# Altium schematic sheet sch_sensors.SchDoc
size Letter
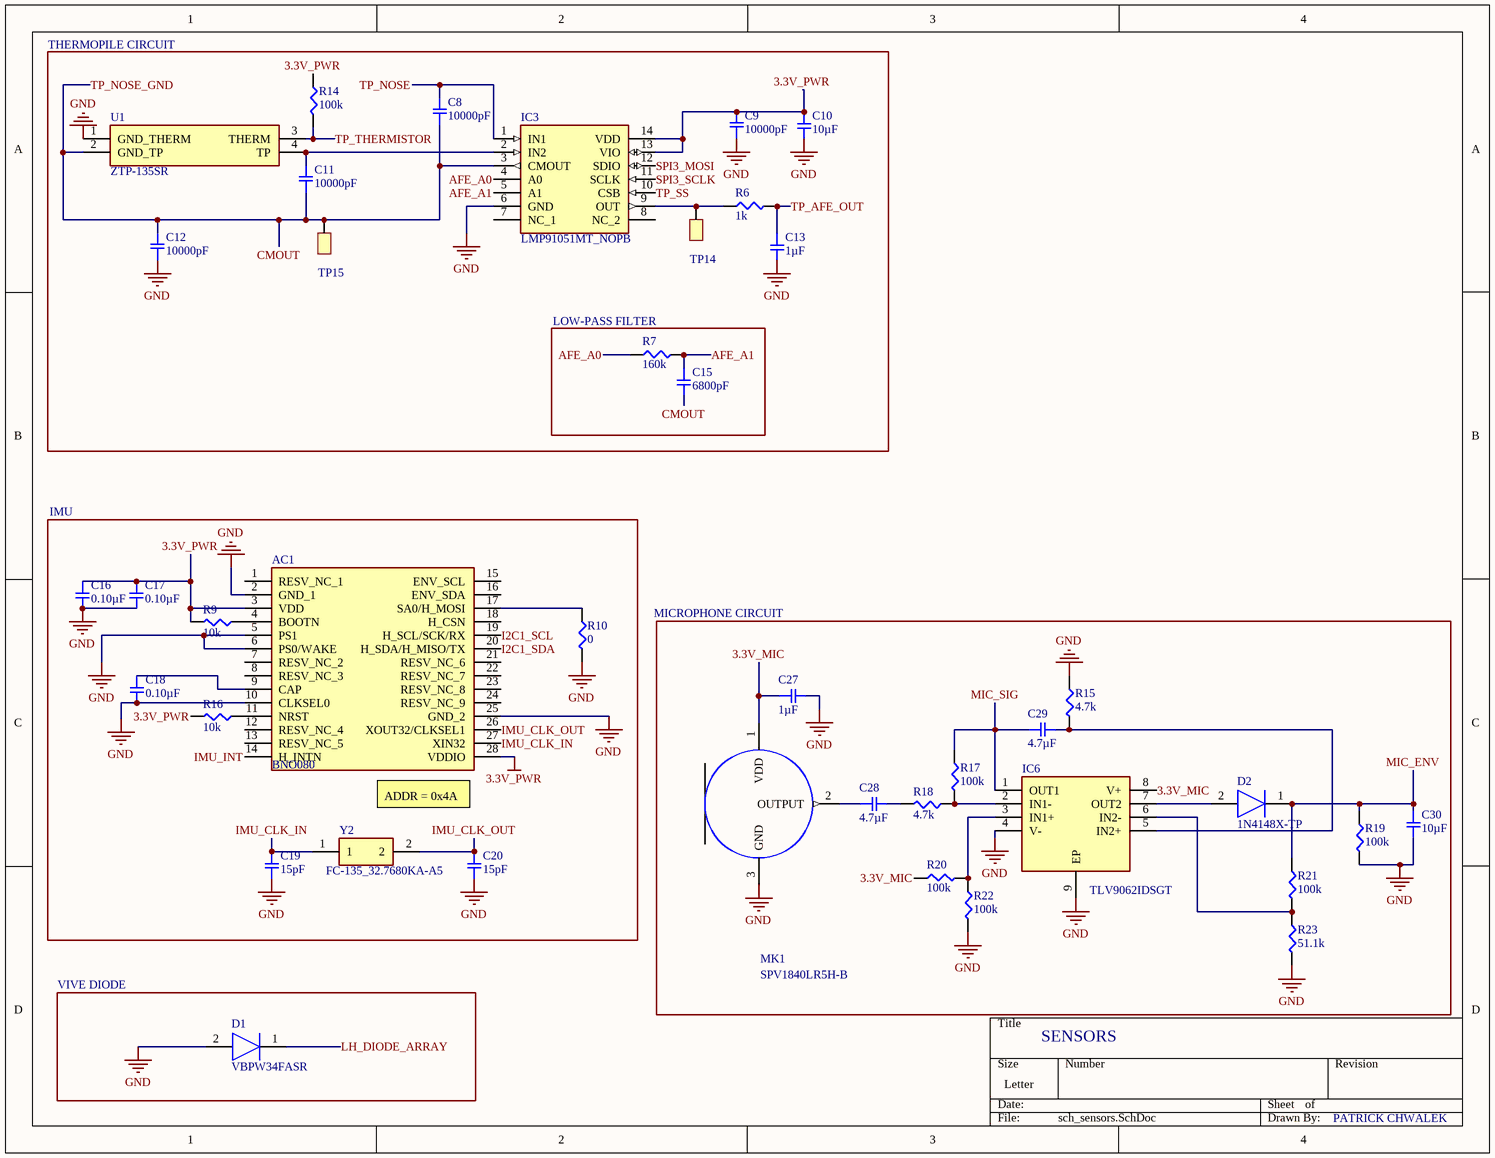
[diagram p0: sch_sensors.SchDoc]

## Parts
AC1  BNO080  [BNO080]
C8  10000pF  [SMD-0402C]
C9  10000pF  [SMD-0402C]
C10  10µF  [SMD-0402C]
C11  10000pF  [SMD-0402C]
C12  10000pF  [SMD-0402C]
C13  1µF  [SMD-0402C]
C15  6800pF  [SMD-0402C]
C16  0.10µF  [CAPC1005X55N]
C17  0.10µF  [CAPC1005X55N]
C18  0.10µF  [CAPC1005X55N]
C19  15pF  [CAPC1005X55N]
C20  15pF  [CAPC1005X55N]
C27  1µF  [SMD-0402-RES]
C28  4.7µF  [SMD-0402C]
C29  4.7µF  [SMD-0402C]
C30  10µF  [SMD-0402C]
D1  VBPW34FASR  [VBPW34FASR]
D2  1N4148X-TP  [SODFL1608X70N]
IC3  LMP91051MT_NOPB  [SOP65P640X120-14N]
IC6  TLV9062IDSGT  [SON50P200X200X80-9N]
MK1  SPV1840LR5H-B  [*MIC_SPV1840LR5H-B]
R6  1k  [SMD-0402-RES]
R7  160k  [SMD-0402-RES]
R9  10k  [SMD-0402-RES]
R10  0  [SMD-0402-RES]
R14  100k  [SMD-0402-RES]
R15  4.7k  [SMD-0402-RES]
R16  10k  [SMD-0402-RES]
R17  100k  [SMD-0402-RES]
R18  4.7k  [SMD-0402-RES]
R19  100k  [SMD-0402-RES]
R20  100k  [SMD-0402-RES]
R21  100k  [SMD-0402-RES]
R22  100k  [SMD-0402-RES]
R23  51.1k  [SMD-0402-RES]
TP14  TestPoint  [TestPoint_0.4mm]  (value not drawn)
TP15  TestPoint  [TestPoint_0.4mm]  (value not drawn)
U1  ZTP-135SR  [ZTP-135SR]
Y2  FC-135_32.7680KA-A5  [FC135327680KAAG0]

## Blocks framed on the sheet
THERMOPILE CIRCUIT: C8-C13 IC3 R6 R14 TP14 TP15 U1
LOW-PASS FILTER: C15 R7
IMU: AC1 C16-C20 R9 R10 R16 Y2
VIVE DIODE: D1

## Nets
3.3V_PWR: AC1.3(VDD) AC1.28(VDDIO) C9.2 C10.1 C16.1 C17.1 IC3.13(VIO) IC3.14(VDD) R9.2 R14.1 R16.2
GND: AC1.2(GND_1) AC1.5(PS1) AC1.6(PS0/WAKE) AC1.10(CLKSEL0) AC1.25(GND_2) C9.1 C10.2 C12.1 C13.2 C16.2 C17.2 C18.2 C19.2 C20.2 C27.2 C30.2 D1.2(K) IC3.6(GND) IC6.4(V-) IC6.9(EP) MK1.3(GND) R10.2 R15.1 R19.2 R22.2 R23.2 U1.1(GND_THERM)
3.3V_MIC: C27.1 IC6.8(V+) MK1.1(VDD) R20.1
AFE_A0: IC3.4(A0) R7.1
AFE_A1: C15.1 IC3.5(A1) R7.2
CMOUT: C8.1 C11.1 C12.2 C15.2 IC3.3(CMOUT) TP15.1 U1.2(GND_TP)  [also labelled TP_NOSE_GND]
I2C1_SCL: AC1.19(H_SCL/SCK/RX)
I2C1_SDA: AC1.20(H_SDA/H_MISO/TX)
IMU_CLK_IN: AC1.27(XIN32) C19.1 Y2.1
IMU_CLK_OUT: AC1.26(XOUT32/CLKSEL1) C20.1 Y2.2
IMU_INT: AC1.14(H_INTN)
LH_DIODE_ARRAY: D1.1(A)
MIC_ENV: C30.1 D2.1(K) R19.1 R21.1
MIC_SIG: C29.1 IC6.1(OUT1) R17.1
SPI3_MOSI: IC3.12(SDIO)
SPI3_SCLK: IC3.11(SCLK)
TP_AFE_OUT: C13.1 R6.2
TP_NOSE: C8.2 IC3.1(IN1)
TP_SS: IC3.10(CSB)
TP_THERMISTOR: R14.2 U1.3(THERM)
NetAC1_4: AC1.4(BOOTN) R9.1
NetAC1_9: AC1.9(CAP) C18.1
NetAC1_11: AC1.11(NRST) R16.1
NetAC1_17: AC1.17(SA0/H_MOSI) R10.1
NetC11_2: C11.2 IC3.2(IN2) U1.4(TP)
NetC28_1: C28.1 MK1.2(OUTPUT)
NetC28_2: C28.2 R18.2
NetC29_2: C29.2 IC6.5(IN2+) R15.2
NetD2_2: D2.2(A) IC6.7(OUT2)
NetIC3_9: IC3.9(OUT) R6.1 TP14.1
NetIC6_2: IC6.2(IN1-) R17.2 R18.1
NetIC6_3: IC6.3(IN1+) R20.2 R22.1
NetIC6_6: IC6.6(IN2-) R21.2 R23.1

Not connected (* = marked no-connect by the designer): AC1 1(RESV_NC_1) 7(RESV_NC_2) 8(RESV_NC_3) 12(RESV_NC_4) 13(RESV_NC_5) 15(ENV_SCL) 16(ENV_SDA) 18(H_CSN) 21(RESV_NC_6) 22(RESV_NC_7) 23(RESV_NC_8) 24(RESV_NC_9); IC3 7(NC_1) 8(NC_2)

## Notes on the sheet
- MICROPHONE CIRCUIT
- (near AC1) ADDR = 0x4A
- SENSORS
- PATRICK CHWALEK

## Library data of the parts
AC1 = BNO080: Accelerometer; Manufacturer_Name: Hillcrest Laboratories
C8 C9 C11 C12 = GCM155R71H103KA55D: CAP CER 10000PF 50V X7R 0402; Manufacturer: Murata Electronics North America; Factory Stock: 0; Unit Price (USD): 0.1; Minimum Quantity: 1; Tolerance: ±10%
C10 C30 = GRJ155R60J106ME11D: CAP CER 10UF 6.3V X5R 0402; Manufacturer: Murata Electronics North America; Factory Stock: 0; Unit Price (USD): 0.23; Minimum Quantity: 1; Tolerance: ±20%
C13 C27 = GCM155C71A105KE38D: CAP CER 1UF 10V X7S 0402; Manufacturer: Murata Electronics North America; Factory Stock: 0; Unit Price (USD): 0.12; Minimum Quantity: 1; Tolerance: ±10%
C15 = GRM155R71E682KA01J: CAP CER 6800PF 25V X7R 0402; Manufacturer: Murata Electronics North America; Factory Stock: 0; Unit Price (USD): 0.1; Minimum Quantity: 1; Tolerance: ±10%
C16-C18 = GCM155R71C104KA55D: CAP CER 0.1UF 16V X7R 0402; Manufacturer: Murata Electronics North America; Factory Stock: 0; Unit Price (USD): 0.1; Minimum Quantity: 1; Tolerance: ±10%
C19 C20 = GCM1555C1H150JA16D: CAP CER 15PF 50V NP0 0402; Manufacturer: Murata Electronics North America; Factory Stock: 0; Unit Price (USD): 0.1; Minimum Quantity: 1; Tolerance: ±5%; Temperature Coefficient: C0G, NP0
C28 C29 = GRM153R60G475ME15D: CAP CER 4.7UF 4V X5R 0402; Manufacturer: Murata Electronics North America; Factory Stock: 0; Unit Price (USD): 0.27; Minimum Quantity: 1; Tolerance: ±20%
D1 = VBPW34FASR: Diode; Manufacturer_Name: Vishay
D2 = 1N4148X-TP: Diode; Manufacturer_Name: Micro Commercial Components (MCC)
IC3 = LMP91051MT_NOPB: Integrated Circuit; Manufacturer_Name: Texas Instruments; Manufacturer_Part_Number: LMP91051MT/NOPB
IC6 = TLV9062IDSGT: Integrated Circuit; Manufacturer_Name: Texas Instruments
MK1 = SPV1840LR5H-B: Mic Mems Analog; MF: Knowles
R6 = ERJ-2GEJ102X: RES SMD 1K OHM 5% 1/10W 0402; Manufacturer: Panasonic Electronic Components; Factory Stock: 0; Unit Price (USD): 0.00350; @ qty: 1500; Minimum Quantity: 1; Power (Watts): 0.1W, 1/10W; Temperature Coefficient: ±200ppm/°C
R7 = ERJ-2GEJ164X: RES SMD 160K OHM 5% 1/10W 0402; Manufacturer: Panasonic Electronic Components; Factory Stock: 0; Unit Price (USD): 0.00350; @ qty: 1500; Minimum Quantity: 1; Power (Watts): 0.1W, 1/10W; Temperature Coefficient: ±200ppm/°C
R9 R16 = ERJ-2GEJ103X: RES SMD 10K OHM 5% 1/10W 0402; Manufacturer: Panasonic Electronic Components; Factory Stock: 0; Unit Price (USD): 0.00350; @ qty: 1500; Minimum Quantity: 1; Power (Watts): 0.1W, 1/10W; Temperature Coefficient: ±200ppm/°C
R10 = ERJ-2GEJ103X: RES SMD 0K OHM 5% 1/10W 0402; Manufacturer: Panasonic Electronic Components; Unit Price (USD): 0.00350; @ qty: 1500; Minimum Quantity: 1; Power (Watts): 0.1W, 1/10W; Temperature Coefficient: ±200ppm/°C
R14 R17 R19-R22 = ERJ-2GEJ103X: RES SMD 100K OHM 5% 1/10W 0402; Manufacturer: Panasonic Electronic Components; Factory Stock: 0; Unit Price (USD): 0.00350; @ qty: 1500; Minimum Quantity: 1; Power (Watts): 0.1W, 1/10W; Temperature Coefficient: ±200ppm/°C
R15 R18 = ERJ-2GEJ103X: RES SMD 4.7K OHM 5% 1/10W 0402; Manufacturer: Panasonic Electronic Components; Factory Stock: 0; Unit Price (USD): 0.00350; @ qty: 1500; Minimum Quantity: 1; Power (Watts): 0.1W, 1/10W; Temperature Coefficient: ±200ppm/°C
R23 = ERJ-2GEJ103X: RES SMD 51.1K OHM 5% 1/10W 0402; Manufacturer: Panasonic Electronic Components; Factory Stock: 0; Unit Price (USD): 0.00350; @ qty: 1500; Minimum Quantity: 1; Power (Watts): 0.1W, 1/10W; Temperature Coefficient: ±200ppm/°C
U1 = ZTP-135SR: Undefined or Miscellaneous; Manufacturer_Name: Amphenol Advanced Sensors; Allied_Number: 70282698
Y2 = FC-135_32.7680KA-A3: Crystal or Oscillator; Manufacturer_Name: Epson Timing; Manufacturer_Part_Number: FC-135 32.7680KA-A5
